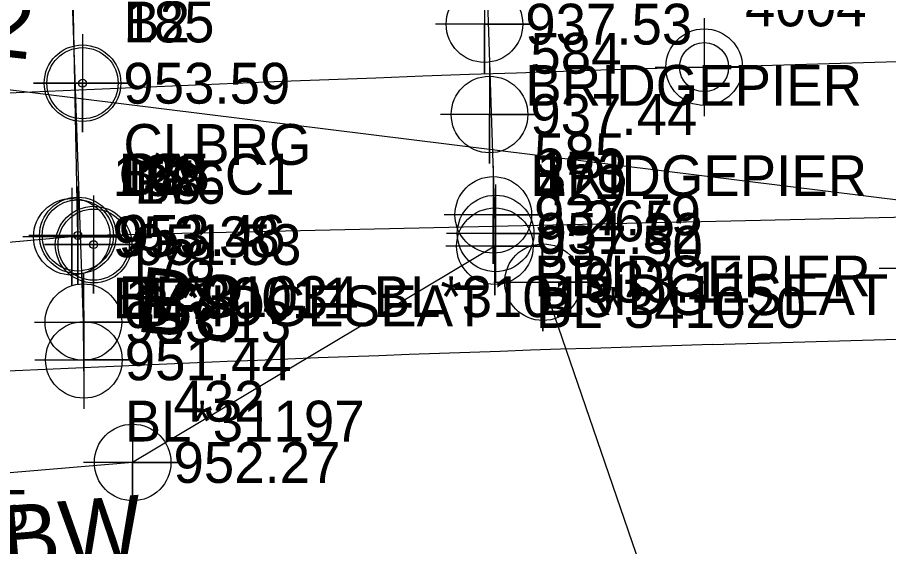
# Model space of a CAD drawing. Extents: x 1150279 to 1151282, y 655434 to 657999.
# Drawn here: x 1150713.8 to 1150767.1, y 657105.1 to 657137.5 of the extents above; entities that cross this region are included whole.
import ezdxf

# ---------------------------------------------------------------- set-up
doc = ezdxf.new("R2010")
doc.units = 0
for name, color, linetype in [('COGO Default Chain', 7, 'Continuous'), ('COGO Default Curve', 7, 'Continuous'), ('Cogo Default Point CELL', 7, 'Continuous'), ('COGO Default Point Elevation', 7, 'Continuous'), ('COGO Default Point Number', 7, 'Continuous'), ('Default Symbol CELL', 7, 'Continuous'), ('Default Symbol Cogo Comment', 7, 'Continuous'), ('Default Symbol Cogo Elevation', 7, 'Continuous'), ('Default Symbol Cogo Number', 7, 'Continuous'), ('Exist Horizontal Alignment', 7, 'Continuous'), ('Exist Horizontal Alignment Station Label', 7, 'Continuous'), ('Exist Hydro Jurisdictional Stream or Body of Water', 7, 'Continuous'), ('Exist Hydro Stream or Body of Water Cogo Elevation', 7, 'Continuous'), ('Exist Hydro Stream or Body of Water Cogo Number', 7, 'Continuous'), ('Exist Hydro Stream or Body of Water Cogo Point CELL', 7, 'Continuous'), ('Exist Other Culture Fence Line', 7, 'Continuous'), ('Exist Other Culture Fence Line Cogo Comment', 7, 'Continuous'), ('Exist Other Culture Fence Line Cogo Elevation', 7, 'Continuous'), ('Exist Other Culture Fence Line Cogo Number', 7, 'Continuous'), ('Exist Other Culture Fence Line Cogo Point CELL', 7, 'Continuous'), ('Exist Other Culture Fence Line Text', 7, 'Continuous'), ('Exist Other Culture Located Object CELL', 7, 'Continuous'), ('Exist Other Culture Located Object Text', 7, 'Continuous'), ('Exist Right of Way Line', 7, 'Continuous'), ('Exist Roads EOP', 7, 'Continuous'), ('Exist Roads EOP Cogo Comment', 7, 'Continuous'), ('Exist Roads EOP Cogo Elevation', 7, 'Continuous'), ('Exist Roads EOP Cogo Number', 7, 'Continuous'), ('Exist Roads EOP Cogo Point CELL', 7, 'Continuous'), ('Exist Structure Major Bridge Seam', 7, 'Continuous'), ('Exist Structure Major Bridge Seam Cogo Comment', 7, 'Continuous'), ('Exist Structure Major Bridge Seam Cogo Elevation', 7, 'Continuous'), ('Exist Structure Major Bridge Seam Cogo Number', 7, 'Continuous'), ('Exist Structure Major Bridge Seam Cogo Point CELL', 7, 'Continuous'), ('Exist Structure Major Bridge WW', 7, 'Continuous'), ('Exist Structure Major Bridge WW Cogo Comment', 7, 'Continuous'), ('Exist Structure Major Bridge WW Cogo Elevation', 7, 'Continuous'), ('Exist Structure Major Bridge WW Cogo Number', 7, 'Continuous'), ('Exist Structure Major Bridge WW Cogo Point CELL', 7, 'Continuous'), ('Exist Structure Major Deck Tunnel Box Culvert', 7, 'Continuous'), ('Exist Structure Major Deck Tunnel Box Culvert Cogo Elevation', 7, 'Continuous'), ('Exist Structure Major Deck Tunnel Box Culvert Cogo Number', 7, 'Continuous'), ('Exist Structure Major Deck Tunnel Box Culvert Cogo Point CELL', 7, 'Continuous'), ('Exist Structure Minor Pipes CMP 15 Inch Cogo Comment', 7, 'Continuous')]:
    doc.layers.add(name, color=color, linetype=linetype)

msp = doc.modelspace()

# ---------------------------------------------------------------- linework, layer by layer
at = {"layer": 'COGO Default Chain'}
for p, q in [((1150614.756, 657145.261), (1150931.292, 657106.062)), ((1150755.797, 657134.446), (1150787.618, 657135.37))]:
    msp.add_line(p, q, dxfattribs=at)
msp.add_arc((1150828.329, 654635.498), 2500, 91.662542, 95.877614, dxfattribs=at)
at = {"layer": 'COGO Default Curve'}
msp.add_arc((1150828.329, 654635.498), 2500, 91.662542, 95.877614, dxfattribs=at)
at = {"layer": 'Cogo Default Point CELL'}
for points in [[(1150755.797, 657137.446), (1150755.797, 657134.446)], [(1150755.797, 657137.446), (1150755.797, 657134.446)], [(1150717.738, 657136.461), (1150717.738, 657133.461)], [(1150752.797, 657134.446), (1150755.797, 657134.446)], [(1150752.797, 657134.446), (1150755.797, 657134.446)], [(1150755.797, 657134.446), (1150758.797, 657134.446)], [(1150755.797, 657134.446), (1150755.797, 657131.446)], [(1150755.797, 657134.446), (1150758.797, 657134.446)], [(1150755.797, 657134.446), (1150755.797, 657131.446)], [(1150714.738, 657133.461), (1150717.738, 657133.461)], [(1150717.738, 657133.461), (1150720.738, 657133.461)], [(1150717.738, 657133.461), (1150717.738, 657130.461)], [(1150717.448, 657127.141), (1150717.448, 657124.141)], [(1150718.416, 657126.579), (1150718.416, 657123.579)], [(1150714.448, 657124.141), (1150717.448, 657124.141)], [(1150717.448, 657124.141), (1150720.448, 657124.141)], [(1150717.448, 657124.141), (1150717.448, 657121.141)], [(1150715.416, 657123.579), (1150718.416, 657123.579)], [(1150718.416, 657123.579), (1150721.416, 657123.579)], [(1150718.416, 657123.579), (1150718.416, 657120.579)]]:
    msp.add_lwpolyline(points, dxfattribs=at)
for centre in [(1150755.797, 657134.446), (1150755.797, 657134.446), (1150717.738, 657133.461), (1150717.448, 657124.141), (1150718.416, 657123.579)]:
    msp.add_circle(centre, 2.344, dxfattribs=at)
at = {"layer": 'Default Symbol CELL'}
for points in [[(1150742.345, 657140.079), (1150742.345, 657134.079), (1150742.345, 657137.079), (1150745.345, 657137.079), (1150739.345, 657137.079)], [(1150717.738, 657136.461), (1150717.738, 657130.461), (1150717.738, 657133.461), (1150720.738, 657133.461), (1150714.738, 657133.461)], [(1150742.655, 657134.545), (1150742.655, 657128.545), (1150742.655, 657131.545), (1150745.655, 657131.545), (1150739.655, 657131.545)], [(1150742.884, 657128.401), (1150742.884, 657122.401), (1150742.884, 657125.401), (1150745.884, 657125.401), (1150739.884, 657125.401)], [(1150743.027, 657127.263), (1150743.027, 657121.263), (1150743.027, 657124.263), (1150746.027, 657124.263), (1150740.027, 657124.263)], [(1150718.416, 657126.579), (1150718.416, 657120.579), (1150718.416, 657123.579), (1150721.416, 657123.579), (1150715.416, 657123.579)]]:
    msp.add_lwpolyline(points, dxfattribs=at)
for centre in [(1150742.345, 657137.079), (1150717.738, 657133.461), (1150742.655, 657131.545), (1150742.884, 657125.401), (1150743.027, 657124.263), (1150718.416, 657123.579)]:
    msp.add_circle(centre, 2.344, dxfattribs=at)
at = {"layer": 'Exist Horizontal Alignment'}
msp.add_line((1150755.797, 657134.446), (1150787.618, 657135.37), dxfattribs=at)
msp.add_arc((1150828.329, 654635.498), 2500, 91.662542, 95.877614, dxfattribs=at)
at = {"layer": 'Exist Horizontal Alignment Station Label'}
msp.add_circle((1150755.797, 657134.446), 1.5, dxfattribs=at)
at = {"layer": 'Exist Hydro Jurisdictional Stream or Body of Water'}
msp.add_lwpolyline([(1150745.794, 657124.778), (1150745.928, 657121.277), (1150758.485, 657084.636), (1150780.666, 657048.192), (1150800.517, 657025.21), (1150816.79, 656993.868)], dxfattribs=at)
at = {"layer": 'Exist Hydro Stream or Body of Water Cogo Point CELL'}
for points in [[(1150766.521, 657122.143), (1150772.521, 657122.143), (1150769.521, 657122.143), (1150769.521, 657119.143), (1150769.521, 657125.143)], [(1150742.928, 657121.277), (1150748.928, 657121.277), (1150745.928, 657121.277), (1150745.928, 657118.277), (1150745.928, 657124.277)]]:
    msp.add_lwpolyline(points, dxfattribs=at)
msp.add_circle((1150745.928, 657121.277), 2.344, dxfattribs=at)
at = {"layer": 'Exist Other Culture Fence Line'}
msp.add_lwpolyline([(1150742.984, 657123.479), (1150720.806, 657110.237), (1150694.904, 657108.057), (1150693.831, 657099.804)], dxfattribs=at)
at = {"layer": 'Exist Other Culture Fence Line Cogo Point CELL'}
for points in [[(1150742.984, 657126.479), (1150742.984, 657120.479), (1150742.984, 657123.479), (1150745.984, 657123.479), (1150739.984, 657123.479)], [(1150720.806, 657113.237), (1150720.806, 657107.237), (1150720.806, 657110.237), (1150723.806, 657110.237), (1150717.806, 657110.237)]]:
    msp.add_lwpolyline(points, dxfattribs=at)
for centre in [(1150742.984, 657123.479), (1150720.806, 657110.237)]:
    msp.add_circle(centre, 2.344, dxfattribs=at)
at = {"layer": 'Exist Other Culture Located Object CELL'}
for centre, radius in [((1150717.738, 657133.461), 2.18), ((1150717.738, 657133.461), 0.24), ((1150717.448, 657124.141), 2.18), ((1150717.448, 657124.141), 0.24)]:
    msp.add_circle(centre, radius, dxfattribs=at)
at = {"layer": 'Exist Other Culture Located Object Text'}
for radius in [2.18, 0.24]:
    msp.add_circle((1150718.416, 657123.579), radius, dxfattribs=at)
at = {"layer": 'Exist Right of Way Line'}
msp.add_line((1150756.29, 657117.453), (1150788.111, 657118.377), dxfattribs=at)
msp.add_arc((1150828.329, 654635.498), 2483, 91.662542, 94.404472, dxfattribs=at)
at = {"layer": 'Exist Roads EOP'}
msp.add_lwpolyline([(1150717.083, 657124.055), (1150672.367, 657120.059), (1150646.285, 657116.941)], dxfattribs=at)
at = {"layer": 'Exist Roads EOP Cogo Point CELL'}
msp.add_lwpolyline([(1150717.083, 657127.055), (1150717.083, 657121.055), (1150717.083, 657124.055), (1150720.083, 657124.055), (1150714.083, 657124.055)], dxfattribs=at)
msp.add_circle((1150717.083, 657124.055), 2.344, dxfattribs=at)
at = {"layer": 'Exist Structure Major Bridge Seam'}
msp.add_line((1150717.448, 657124.141), (1150717.083, 657143.072), dxfattribs=at)
at = {"layer": 'Exist Structure Major Bridge Seam Cogo Point CELL'}
msp.add_lwpolyline([(1150717.448, 657127.141), (1150717.448, 657121.141), (1150717.448, 657124.141), (1150720.448, 657124.141), (1150714.448, 657124.141)], dxfattribs=at)
msp.add_circle((1150717.448, 657124.141), 2.344, dxfattribs=at)
at = {"layer": 'Exist Structure Major Bridge WW'}
msp.add_lwpolyline([(1150717.82, 657116.521), (1150717.792, 657118.834), (1150716.802, 657148.017), (1150716.973, 657149.946)], dxfattribs=at)
at = {"layer": 'Exist Structure Major Bridge WW Cogo Point CELL'}
for points in [[(1150714.792, 657118.834), (1150720.792, 657118.834), (1150717.792, 657118.834), (1150717.792, 657121.834), (1150717.792, 657115.834)], [(1150714.82, 657116.521), (1150720.82, 657116.521), (1150717.82, 657116.521), (1150717.82, 657119.521), (1150717.82, 657113.521)]]:
    msp.add_lwpolyline(points, dxfattribs=at)
for centre in [(1150717.792, 657118.834), (1150717.82, 657116.521)]:
    msp.add_circle(centre, 2.344, dxfattribs=at)
at = {"layer": 'Exist Structure Major Deck Tunnel Box Culvert'}
msp.add_line((1150717.448, 657124.141), (1150798.272, 657125.958), dxfattribs=at)
msp.add_lwpolyline([(1150743.027, 657124.263), (1150742.363, 657144.022)], dxfattribs=at)
at = {"layer": 'Exist Structure Major Deck Tunnel Box Culvert Cogo Point CELL'}
msp.add_lwpolyline([(1150714.448, 657124.141), (1150720.448, 657124.141), (1150717.448, 657124.141), (1150717.448, 657127.141), (1150717.448, 657121.141)], dxfattribs=at)
msp.add_circle((1150717.448, 657124.141), 2.344, dxfattribs=at)

# ---------------------------------------------------------------- texts
at = {"layer": 'COGO Default Point Elevation'}
for s, p in [('953.59', (1150720.238, 657132.211)), ('953.46', (1150719.948, 657122.891)), ('951.53', (1150720.916, 657122.329))]:
    msp.add_text(s, height=2.5, dxfattribs=at).set_placement(p)
at = {"layer": 'COGO Default Point Number'}
for s, p in [('4004', (1150758.297, 657136.946)), ('B2', (1150720.238, 657135.961)), ('B3', (1150719.948, 657126.641)), ('B8', (1150720.916, 657126.079))]:
    msp.add_text(s, height=2.5, dxfattribs=at).set_placement(p)
at = {"layer": 'Default Symbol Cogo Comment'}
for s, p in [('BRIDGEPIER', (1150744.845, 657132.079)), ('CLBRG', (1150720.238, 657128.461)), ('BRIDGEPIER', (1150745.155, 657126.545)), ('BRIDGEPIER', (1150745.384, 657120.401)), ('BRIDGESEAT', (1150745.527, 657119.263)), ('BRIDGESEAT', (1150720.916, 657118.579))]:
    msp.add_text(s, height=2.5, dxfattribs=at).set_placement(p)
at = {"layer": 'Default Symbol Cogo Elevation'}
for s, p in [('937.53', (1150744.845, 657135.829)), ('953.59', (1150720.238, 657132.211)), ('937.44', (1150745.155, 657130.295)), ('937.79', (1150745.384, 657124.151)), ('951.32', (1150745.527, 657123.013)), ('951.53', (1150720.916, 657122.329))]:
    msp.add_text(s, height=2.5, dxfattribs=at).set_placement(p)
at = {"layer": 'Default Symbol Cogo Number'}
for s, p in [('185', (1150720.238, 657135.961)), ('584', (1150745.155, 657134.045)), ('585', (1150745.384, 657127.901)), ('173', (1150745.527, 657126.763)), ('176', (1150720.916, 657126.079))]:
    msp.add_text(s, height=2.5, dxfattribs=at).set_placement(p)
at = {"layer": 'Exist Hydro Stream or Body of Water Cogo Elevation'}
msp.add_text('933.11', height=2.5, dxfattribs=at).set_placement((1150748.428, 657120.027))
at = {"layer": 'Exist Hydro Stream or Body of Water Cogo Number'}
msp.add_text('265', height=2.5, dxfattribs=at).set_placement((1150748.428, 657123.777))
at = {"layer": 'Exist Other Culture Fence Line Cogo Comment'}
msp.add_text('BL*341020', height=2.5, dxfattribs=at).set_placement((1150745.484, 657118.479))
at = {"layer": 'Exist Other Culture Fence Line Cogo Elevation'}
for s, p in [('937.50', (1150745.484, 657122.229)), ('952.27', (1150723.306, 657108.987))]:
    msp.add_text(s, height=2.5, dxfattribs=at).set_placement(p)
at = {"layer": 'Exist Other Culture Fence Line Cogo Number'}
for s, p in [('429', (1150745.484, 657125.979)), ('432', (1150723.306, 657112.737))]:
    msp.add_text(s, height=2.5, dxfattribs=at).set_placement(p)
at = {"layer": 'Exist Other Culture Fence Line Text'}
msp.add_text('4SBW', height=4, rotation=4.8118, dxfattribs=at).set_placement((1150706.414, 657103.004))
at = {"layer": 'Exist Other Culture Located Object Text'}
for s, p in [('B2', (1150708.024, 657135.634)), ('B8', (1150720.891, 657118.278))]:
    msp.add_text(s, height=4, rotation=353.6867, dxfattribs=at).set_placement(p)
at = {"layer": 'Exist Roads EOP Cogo Comment'}
msp.add_text('BL*30011', height=2.5, dxfattribs=at).set_placement((1150719.583, 657119.055))
at = {"layer": 'Exist Roads EOP Cogo Elevation'}
msp.add_text('953.38', height=2.5, dxfattribs=at).set_placement((1150719.583, 657122.805))
at = {"layer": 'Exist Roads EOP Cogo Number'}
msp.add_text('133', height=2.5, dxfattribs=at).set_placement((1150719.583, 657126.555))
at = {"layer": 'Exist Structure Major Bridge Seam Cogo Comment'}
msp.add_text('BL*31034 BL*31015', height=2.5, dxfattribs=at).set_placement((1150719.948, 657119.141))
at = {"layer": 'Exist Structure Major Bridge Seam Cogo Elevation'}
msp.add_text('953.46', height=2.5, dxfattribs=at).set_placement((1150719.948, 657122.891))
at = {"layer": 'Exist Structure Major Bridge Seam Cogo Number'}
msp.add_text('165', height=2.5, dxfattribs=at).set_placement((1150719.948, 657126.641))
at = {"layer": 'Exist Structure Major Bridge WW Cogo Comment'}
msp.add_text('BL*31197', height=2.5, dxfattribs=at).set_placement((1150720.32, 657111.521))
at = {"layer": 'Exist Structure Major Bridge WW Cogo Elevation'}
for s, p in [('953.13', (1150720.292, 657117.584)), ('951.44', (1150720.32, 657115.271))]:
    msp.add_text(s, height=2.5, dxfattribs=at).set_placement(p)
at = {"layer": 'Exist Structure Major Bridge WW Cogo Number'}
for s, p in [('178', (1150720.292, 657121.334)), ('177', (1150720.32, 657119.021))]:
    msp.add_text(s, height=2.5, dxfattribs=at).set_placement(p)
at = {"layer": 'Exist Structure Major Deck Tunnel Box Culvert Cogo Elevation'}
msp.add_text('953.46', height=2.5, dxfattribs=at).set_placement((1150719.948, 657122.891))
at = {"layer": 'Exist Structure Major Deck Tunnel Box Culvert Cogo Number'}
msp.add_text('CALC1', height=2.5, dxfattribs=at).set_placement((1150719.948, 657126.641))
at = {"layer": 'Exist Structure Minor Pipes CMP 15 Inch Cogo Comment'}
msp.add_text('BL*521525', height=2.5, dxfattribs=at).set_placement((1150697.911, 657106.053))

doc.saveas('drawing.dxf')
